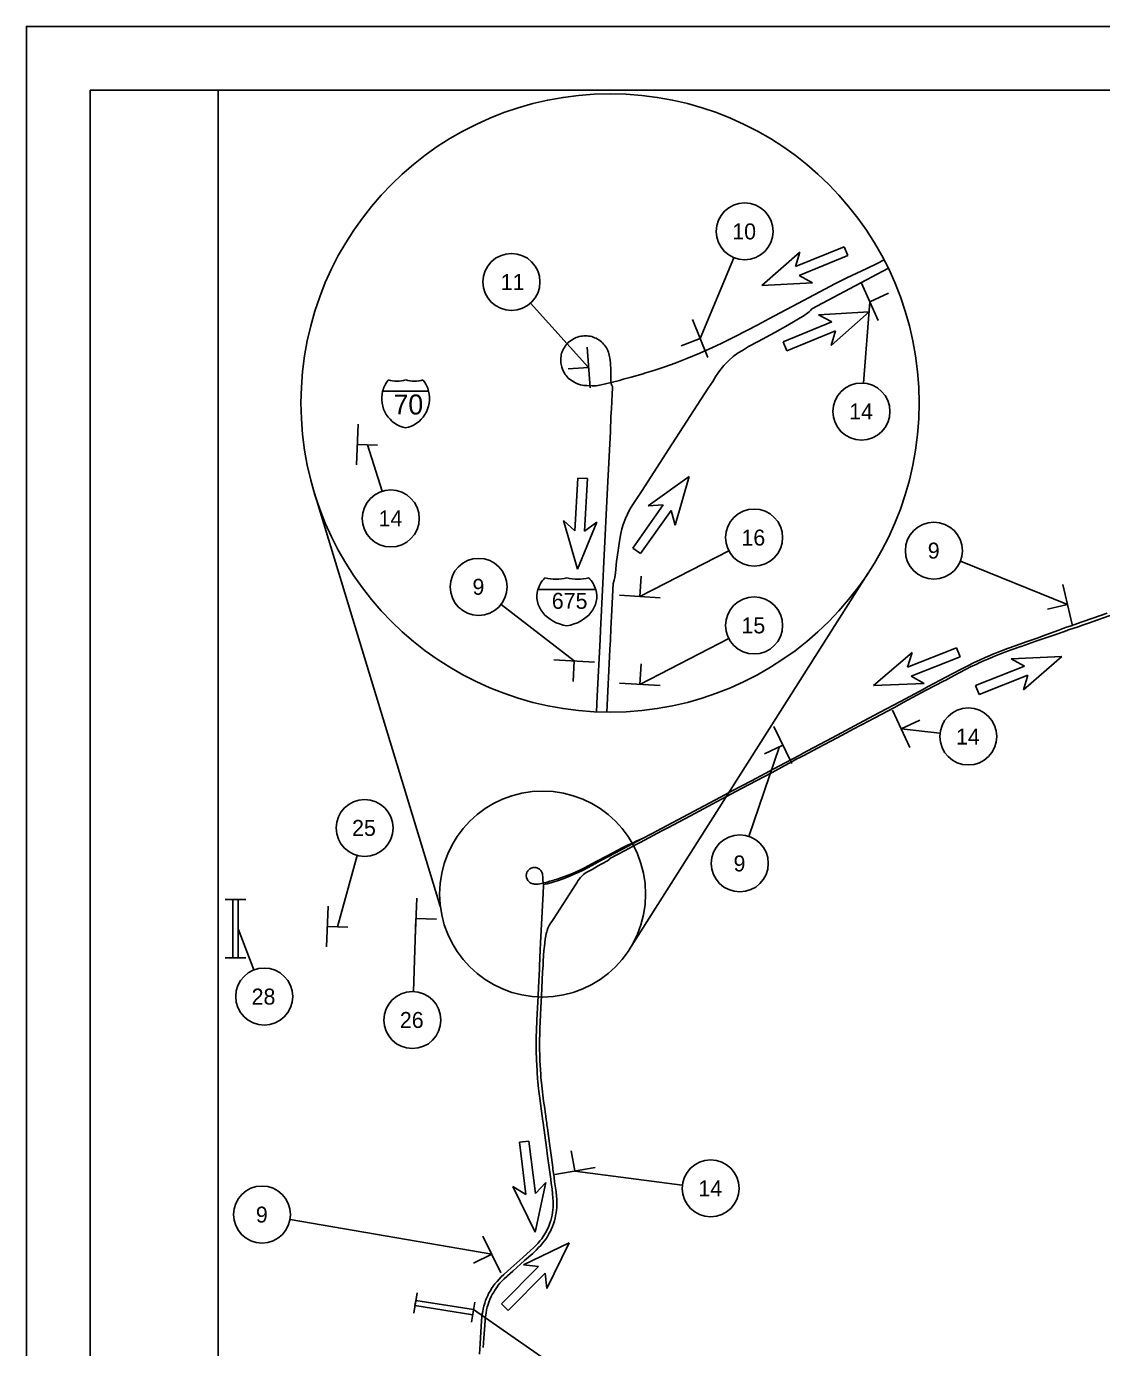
# Model space of a CAD drawing. Extents: x 632.2 to 666.2, y -36.3 to -14.3.
# Drawn here: x 632.19 to 640.6, y -24.64 to -14.3 of the extents above; entities that cross this region are included whole.
import ezdxf

# ---------------------------------------------------------------- set-up
doc = ezdxf.new("R2010")
doc.units = 0
for name, color, linetype in [('Default', 7, 'Continuous'), ('GM_X_Township_ROW', 7, 'Continuous'), ('GM_X_Township_Subdivision', 7, 'Continuous'), ('MT_P_Cells', 7, 'Continuous'), ('SH_Border', 7, 'Continuous'), ('SH_Cut_Line', 7, 'Continuous'), ('SH_Text', 7, 'Continuous'), ('SN_P_Signs', 7, 'Continuous')]:
    doc.layers.add(name, color=color, linetype=linetype)

msp = doc.modelspace()

# ---------------------------------------------------------------- linework, layer by layer
at = {"layer": 'Default'}
for centre in [(637.808, -15.906), (635.983, -16.302), (638.722, -17.316), (635.039, -18.153), (637.882, -18.302), (639.289, -18.405), (635.726, -18.688), (637.882, -18.99), (639.558, -19.859), (634.834, -20.575), (637.77, -20.852), (634.048, -21.894), (635.208, -22.078), (637.542, -23.395), (634.031, -23.6)]:
    msp.add_circle(centre, 0.223, dxfattribs=at)
at = {"layer": 'GM_X_Township_ROW'}
for p, q in [((634.975, -17.157), (635.335, -17.157)), ((635.335, -17.157), (634.975, -17.157)), ((635.335, -17.157), (634.975, -17.157)), ((636.643, -18.709), (636.19, -18.709)), ((636.643, -18.709), (636.19, -18.709))]:
    msp.add_line(p, q, dxfattribs=at)
for centre, start, end in [((635.202, -17.215), 165.8066, 258.463), ((635.202, -17.215), 141.669, 165.8066), ((635.087, -16.845), 253.0091, 286.9909), ((635.224, -16.845), 253.0091, 286.9909), ((635.108, -17.215), 281.537, 14.1934), ((635.108, -17.215), 14.1934, 38.331)]:
    msp.add_arc(centre, 0.234, start, end, dxfattribs=at)
for centre, start_param, end_param in [((636.475, -18.763), 2.911027, 4.511031), ((636.475, -18.763), 2.47259, 2.911027), ((636.331, -18.393), 4.415841, 5.008937), ((636.502, -18.393), 4.415841, 5.008937), ((636.358, -18.763), 4.913747, 6.513751), ((636.358, -18.763), 0.230566, 0.669003)]:
    msp.add_ellipse(centre, major_axis=(0.293, 0), ratio=0.8, start_param=start_param, end_param=end_param, dxfattribs=at)
at = {"layer": 'GM_X_Township_Subdivision'}
for p, q in [((637.942, -16.33), (638.24, -16.068)), ((638.206, -16.182), (638.587, -16.026)), ((638.24, -16.068), (638.206, -16.182)), ((638.616, -16.095), (638.234, -16.251)), ((638.587, -16.026), (638.616, -16.095)), ((638.602, -16.061), (638.602, -16.061)), ((638.338, -16.309), (637.942, -16.33)), ((637.942, -16.33), (637.942, -16.33)), ((638.234, -16.251), (638.338, -16.309)), ((638.387, -16.558), (638.783, -16.537)), ((638.783, -16.537), (638.485, -16.799)), ((638.783, -16.537), (638.783, -16.537)), ((638.109, -16.771), (638.491, -16.615)), ((638.491, -16.615), (638.387, -16.558)), ((638.52, -16.685), (638.138, -16.841)), ((638.485, -16.799), (638.52, -16.685)), ((638.138, -16.841), (638.109, -16.771)), ((638.124, -16.806), (638.124, -16.806)), ((636.479, -18.249), (636.502, -17.837)), ((636.502, -17.837), (636.577, -17.841)), ((636.54, -17.839), (636.54, -17.839)), ((636.577, -17.841), (636.554, -18.253)), ((637.052, -18.055), (637.375, -17.824)), ((637.375, -17.824), (637.265, -18.205)), ((637.375, -17.824), (637.375, -17.824)), ((636.933, -18.384), (637.171, -18.047)), ((637.232, -18.09), (636.994, -18.427)), ((637.171, -18.047), (637.052, -18.055)), ((637.265, -18.205), (637.232, -18.09)), ((636.499, -18.55), (636.39, -18.169)), ((636.39, -18.169), (636.479, -18.249)), ((636.65, -18.183), (636.499, -18.55)), ((636.554, -18.253), (636.65, -18.183)), ((636.994, -18.427), (636.933, -18.384)), ((636.963, -18.406), (636.963, -18.406)), ((636.499, -18.55), (636.499, -18.55)), ((638.817, -19.461), (639.119, -19.202)), ((639.083, -19.316), (639.467, -19.165)), ((639.119, -19.202), (639.083, -19.316)), ((639.467, -19.165), (639.494, -19.235)), ((639.48, -19.2), (639.48, -19.2)), ((639.494, -19.235), (639.11, -19.386)), ((639.614, -19.461), (639.998, -19.309)), ((639.894, -19.251), (640.291, -19.234)), ((639.998, -19.309), (639.894, -19.251)), ((640.291, -19.234), (639.99, -19.493)), ((640.291, -19.234), (640.291, -19.234)), ((639.11, -19.386), (639.214, -19.445)), ((640.025, -19.379), (639.642, -19.53)), ((639.99, -19.493), (640.025, -19.379)), ((639.214, -19.445), (638.817, -19.461)), ((638.817, -19.461), (638.817, -19.461)), ((639.642, -19.53), (639.614, -19.461)), ((639.628, -19.496), (639.628, -19.496)), ((636.046, -23.034), (636.12, -23.025)), ((636.095, -23.444), (636.046, -23.034)), ((636.083, -23.03), (636.083, -23.03)), ((636.12, -23.025), (636.17, -23.435)), ((636.253, -23.349), (636.169, -23.737)), ((636.17, -23.435), (636.253, -23.349)), ((636.169, -23.737), (635.994, -23.38)), ((635.994, -23.38), (636.095, -23.444)), ((636.169, -23.737), (636.169, -23.737)), ((636.077, -23.994), (636.434, -23.821)), ((636.434, -23.821), (636.261, -24.178)), ((636.434, -23.821), (636.434, -23.821)), ((635.904, -24.298), (636.195, -24.006)), ((636.248, -24.059), (635.957, -24.351)), ((636.195, -24.006), (636.077, -23.994)), ((636.261, -24.178), (636.248, -24.059)), ((635.957, -24.351), (635.904, -24.298)), ((635.93, -24.325), (635.93, -24.325))]:
    msp.add_line(p, q, dxfattribs=at)
at = {"layer": 'MT_P_Cells'}
for p, q in [((633.744, -21.134), (633.904, -21.134)), ((633.824, -21.363), (633.824, -21.363)), ((633.744, -21.592), (633.904, -21.592)), ((635.244, -24.213), (635.219, -24.371)), ((635.696, -24.285), (635.671, -24.443)), ((635.457, -24.328), (635.457, -24.328))]:
    msp.add_line(p, q, dxfattribs=at)
for points in [[(633.804, -21.134), (633.844, -21.134), (633.844, -21.592), (633.804, -21.592)], [(635.687, -24.344), (635.681, -24.384), (635.228, -24.311), (635.234, -24.272)]]:
    msp.add_lwpolyline(points, close=True, dxfattribs=at)
at = {"layer": 'SH_Border'}
for points in [[(632.687, -14.802), (633.687, -14.802), (633.687, -35.802), (632.687, -35.802)], [(633.687, -14.802), (665.687, -14.802), (665.687, -35.802), (633.687, -35.802)]]:
    msp.add_lwpolyline(points, close=True, dxfattribs=at)
at = {"layer": 'SH_Cut_Line'}
msp.add_lwpolyline([(632.187, -36.302), (666.187, -36.302), (666.187, -14.302), (632.187, -14.302)], close=True, dxfattribs=at)
at = {"layer": 'SH_Text'}
for p, q in [((637.723, -16.112), (637.461, -16.744)), ((636.133, -16.468), (636.587, -16.971)), ((638.739, -17.093), (638.788, -16.457)), ((634.971, -17.94), (634.856, -17.577)), ((635.426, -21.187), (634.441, -17.954)), ((637.683, -18.405), (636.988, -18.763)), ((639.496, -18.488), (640.335, -18.826)), ((636.908, -21.524), (638.773, -18.583)), ((635.903, -18.825), (636.474, -19.268)), ((637.683, -19.092), (636.988, -19.451)), ((639.336, -19.834), (639.033, -19.799)), ((637.841, -20.641), (638.08, -19.938)), ((634.775, -20.79), (634.622, -21.349)), ((635.216, -21.855), (635.236, -21.283)), ((633.968, -21.686), (633.844, -21.363)), ((637.32, -23.37), (636.478, -23.261)), ((634.251, -23.638), (635.829, -23.911)), ((636.502, -24.909), (635.687, -24.344))]:
    msp.add_line(p, q, dxfattribs=at)
for points in [[(636.649, -19.666), (636.655, -19.544), (636.678, -19.099), (636.681, -19.029), (636.697, -18.66), (636.706, -18.493), (636.735, -17.914), (636.757, -17.471), (636.762, -17.354), (636.765, -17.296), (636.77, -17.181), (636.773, -17.13), (636.773, -17.125), (636.773, -17.117), (636.768, -17.111), (636.766, -17.105), (636.764, -17.096), (636.764, -17.088), (636.762, -17.076), (636.76, -17.019), (636.76, -16.998), (636.757, -16.936), (636.753, -16.899), (636.749, -16.875), (636.742, -16.851), (636.738, -16.839), (636.732, -16.828), (636.726, -16.817), (636.72, -16.807), (636.712, -16.797), (636.704, -16.788), (636.696, -16.779), (636.687, -16.77), (636.677, -16.763), (636.667, -16.755), (636.657, -16.749), (636.646, -16.743), (636.634, -16.738), (636.623, -16.734), (636.611, -16.73), (636.599, -16.727), (636.587, -16.725), (636.575, -16.724), (636.562, -16.723), (636.55, -16.724), (636.537, -16.725), (636.525, -16.727), (636.513, -16.729), (636.501, -16.733), (636.49, -16.737), (636.479, -16.742), (636.468, -16.748), (636.457, -16.754), (636.437, -16.769), (636.428, -16.777), (636.419, -16.786), (636.411, -16.795), (636.403, -16.805), (636.397, -16.815), (636.39, -16.826), (636.385, -16.837), (636.38, -16.848), (636.376, -16.86), (636.373, -16.872), (636.371, -16.884), (636.37, -16.897), (636.369, -16.909), (636.369, -16.921), (636.37, -16.934), (636.372, -16.946), (636.374, -16.958), (636.377, -16.97), (636.386, -16.993), (636.397, -17.015), (636.404, -17.025), (636.411, -17.035), (636.419, -17.045), (636.428, -17.054), (636.437, -17.062), (636.457, -17.077), (636.478, -17.089), (636.501, -17.099), (636.524, -17.106), (636.549, -17.111), (636.561, -17.112), (636.573, -17.113), (636.615, -17.114), (636.646, -17.115), (636.684, -17.107), (636.764, -17.088), (636.775, -17.086), (636.828, -17.073), (636.858, -17.064), (636.921, -17.046), (637.013, -17.02), (637.023, -17.017), (637.098, -16.995), (637.184, -16.966), (637.263, -16.937), (637.355, -16.902), (637.458, -16.86), (637.557, -16.815), (637.625, -16.783), (637.733, -16.728), (637.91, -16.638), (637.998, -16.591), (638.269, -16.446), (638.52, -16.314), (638.608, -16.27), (638.764, -16.196), (638.846, -16.157), (638.901, -16.13)], [(638.333, -16.513), (638.674, -16.333), (638.933, -16.195)], [(636.779, -18.661), (636.788, -18.636), (636.793, -18.614), (636.798, -18.578), (636.806, -18.49), (636.817, -18.404), (636.828, -18.331), (636.839, -18.27), (636.848, -18.234), (636.858, -18.199), (636.875, -18.152), (636.891, -18.119), (636.908, -18.086), (636.933, -18.044), (637.001, -17.941), (637.242, -17.568), (637.523, -17.133), (637.558, -17.082), (637.583, -17.039), (637.614, -16.994), (637.644, -16.957), (637.681, -16.918), (637.717, -16.886), (637.757, -16.857), (637.79, -16.838), (637.838, -16.808), (637.913, -16.768), (638.044, -16.697), (638.146, -16.64), (638.275, -16.564), (638.303, -16.544), (638.314, -16.536), (638.323, -16.526), (638.333, -16.513)], [(640.418, -19), (640.452, -18.989), (640.498, -18.973), (640.571, -18.947), (640.66, -18.916), (640.738, -18.888), (640.778, -18.875), (640.807, -18.864), (640.877, -18.84), (641.016, -18.791), (641.178, -18.734), (641.364, -18.669), (641.43, -18.646), (641.48, -18.629), (641.512, -18.619), (641.543, -18.61), (641.583, -18.6), (641.619, -18.592), (641.651, -18.586), (641.68, -18.581), (641.712, -18.576), (641.748, -18.572)], [(636.729, -19.668), (636.754, -19.178), (636.758, -19.103), (636.762, -19.015), (636.767, -18.921), (636.779, -18.661)], [(636.234, -21.018), (636.261, -21.011), (636.263, -21.011), (636.291, -21.003), (636.322, -20.994), (636.35, -20.985), (636.381, -20.975), (636.415, -20.962), (636.45, -20.948), (636.48, -20.935), (636.51, -20.921), (636.539, -20.907), (636.583, -20.884), (636.688, -20.828), (636.847, -20.744), (636.97, -20.678), (637.009, -20.658), (637.079, -20.621), (637.452, -20.422), (637.618, -20.333), (637.709, -20.285), (637.861, -20.205), (638.075, -20.091), (638.234, -20.007), (638.239, -20.004), (638.248, -19.999), (638.295, -19.974), (638.448, -19.893), (638.531, -19.849), (638.701, -19.757), (638.864, -19.671), (639.027, -19.585), (639.214, -19.485), (639.24, -19.471), (639.436, -19.367), (639.498, -19.335), (639.549, -19.309), (639.604, -19.281), (639.645, -19.262), (639.689, -19.242), (639.734, -19.222), (639.738, -19.221), (639.772, -19.206), (639.818, -19.188), (639.864, -19.171), (639.933, -19.146), (640.011, -19.119), (640.096, -19.089), (640.166, -19.063), (640.267, -19.026), (640.319, -19.007), (640.346, -18.998), (640.354, -18.995), (640.448, -18.962), (640.533, -18.932), (640.645, -18.893)], [(640.331, -19.03), (640.335, -19.028), (640.343, -19.025), (640.418, -19)], [(639.969, -19.155), (639.971, -19.155), (640.029, -19.134), (640.087, -19.114), (640.188, -19.079), (640.25, -19.057), (640.331, -19.03)], [(639.711, -19.253), (639.721, -19.249), (639.729, -19.245), (639.771, -19.227), (639.771, -19.227)], [(639.771, -19.227), (639.809, -19.212), (639.843, -19.199), (639.901, -19.179), (639.969, -19.155)], [(639.368, -19.424), (639.376, -19.42), (639.448, -19.381), (639.536, -19.335), (639.576, -19.315), (639.624, -19.292), (639.638, -19.285)], [(639.638, -19.285), (639.673, -19.27), (639.711, -19.253)], [(639.054, -19.591), (639.224, -19.5), (639.368, -19.424)], [(638.646, -19.808), (638.728, -19.765), (638.826, -19.712), (638.98, -19.631)], [(638.98, -19.631), (639.018, -19.61), (639.054, -19.591)], [(637.213, -20.57), (637.251, -20.55), (637.385, -20.479), (637.555, -20.388), (637.631, -20.348), (637.74, -20.29), (637.837, -20.238), (638.022, -20.14), (638.152, -20.07), (638.185, -20.053), (638.217, -20.035), (638.24, -20.023), (638.272, -20.007), (638.377, -19.951), (638.533, -19.869), (638.634, -19.814), (638.646, -19.808)], [(636.991, -20.688), (637.161, -20.598), (637.213, -20.57)], [(636.208, -22.711), (636.202, -22.671), (636.198, -22.634), (636.195, -22.614), (636.193, -22.59), (636.189, -22.557), (636.188, -22.541), (636.186, -22.524), (636.184, -22.499), (636.183, -22.475), (636.178, -22.39), (636.176, -22.32), (636.176, -22.247), (636.177, -22.21), (636.178, -22.16), (636.182, -22.078), (636.191, -21.889), (636.194, -21.824), (636.202, -21.676), (636.203, -21.653), (636.208, -21.53), (636.211, -21.474), (636.221, -21.281), (636.228, -21.133), (636.23, -21.094), (636.231, -21.075), (636.233, -21.037), (636.234, -21.02), (636.234, -21.018), (636.234, -21.015), (636.232, -21.013), (636.231, -21.011), (636.231, -21.008), (636.23, -21.006), (636.23, -21.002), (636.229, -20.983), (636.229, -20.976), (636.228, -20.955), (636.227, -20.943), (636.226, -20.935), (636.223, -20.927), (636.222, -20.923), (636.22, -20.919), (636.218, -20.916), (636.216, -20.912), (636.213, -20.909), (636.211, -20.906), (636.208, -20.903), (636.205, -20.9), (636.202, -20.897), (636.198, -20.895), (636.195, -20.893), (636.191, -20.891), (636.187, -20.889), (636.184, -20.888), (636.18, -20.886), (636.176, -20.885), (636.172, -20.885), (636.167, -20.884), (636.163, -20.884), (636.159, -20.884), (636.155, -20.885), (636.151, -20.885), (636.147, -20.886), (636.143, -20.887), (636.139, -20.889), (636.135, -20.89), (636.132, -20.892), (636.128, -20.895), (636.122, -20.899), (636.119, -20.902), (636.116, -20.905), (636.113, -20.908), (636.11, -20.911), (636.108, -20.915), (636.106, -20.918), (636.104, -20.922), (636.103, -20.926), (636.101, -20.93), (636.1, -20.934), (636.1, -20.938), (636.099, -20.942), (636.099, -20.946), (636.099, -20.95), (636.099, -20.954), (636.1, -20.958), (636.101, -20.962), (636.102, -20.966), (636.105, -20.974), (636.108, -20.981), (636.111, -20.985), (636.113, -20.988), (636.116, -20.991), (636.119, -20.994), (636.122, -20.997), (636.128, -21.002), (636.135, -21.006), (636.143, -21.009), (636.151, -21.012), (636.159, -21.013), (636.163, -21.014), (636.167, -21.014), (636.181, -21.014), (636.191, -21.015), (636.204, -21.012), (636.23, -21.006), (636.234, -21.005), (636.252, -21.001), (636.262, -20.998), (636.283, -20.992), (636.314, -20.983), (636.317, -20.982), (636.342, -20.975), (636.37, -20.965), (636.397, -20.955), (636.428, -20.944), (636.462, -20.93), (636.495, -20.915), (636.518, -20.904), (636.554, -20.886), (636.613, -20.856), (636.642, -20.84), (636.732, -20.792), (636.816, -20.748), (636.845, -20.733), (636.897, -20.708), (636.924, -20.696), (636.963, -20.676), (636.99, -20.664), (637, -20.661), (637.009, -20.658)], [(636.753, -20.814), (636.867, -20.754), (636.965, -20.702), (636.991, -20.688)], [(636.236, -21.53), (636.238, -21.522), (636.24, -21.514), (636.242, -21.502), (636.245, -21.473), (636.248, -21.444), (636.252, -21.42), (636.256, -21.4), (636.259, -21.388), (636.262, -21.376), (636.268, -21.36), (636.273, -21.349), (636.279, -21.338), (636.287, -21.324), (636.309, -21.29), (636.39, -21.166), (636.483, -21.021), (636.495, -21.004), (636.503, -20.989), (636.514, -20.975), (636.524, -20.962), (636.536, -20.949), (636.548, -20.939), (636.561, -20.929), (636.572, -20.922), (636.589, -20.912), (636.614, -20.899), (636.657, -20.875), (636.691, -20.856), (636.734, -20.831), (636.744, -20.825), (636.747, -20.822), (636.75, -20.818), (636.753, -20.814)], [(636.212, -22.501), (636.207, -22.432), (636.206, -22.398), (636.204, -22.363), (636.204, -22.34), (636.203, -22.32), (636.203, -22.3), (636.203, -22.273), (636.203, -22.239), (636.203, -22.22), (636.204, -22.201), (636.204, -22.186), (636.206, -22.145), (636.216, -21.931), (636.218, -21.892), (636.227, -21.702), (636.229, -21.677), (636.23, -21.648), (636.232, -21.617), (636.236, -21.53)], [(636.235, -22.714), (636.22, -22.592), (636.214, -22.528), (636.212, -22.501)], [(635.732, -24.692), (635.737, -24.609), (635.746, -24.475), (635.749, -24.433), (635.752, -24.403), (635.755, -24.378), (635.758, -24.359), (635.762, -24.337), (635.768, -24.316), (635.774, -24.294), (635.781, -24.273), (635.789, -24.254), (635.797, -24.234), (635.807, -24.214), (635.818, -24.196), (635.828, -24.178), (635.84, -24.161), (635.854, -24.143), (635.87, -24.124), (635.886, -24.105), (635.903, -24.088), (635.923, -24.068), (635.954, -24.041), (636.073, -23.935), (636.133, -23.881), (636.155, -23.86), (636.174, -23.842), (636.191, -23.823), (636.206, -23.806), (636.22, -23.789), (636.231, -23.772), (636.25, -23.744), (636.268, -23.709), (636.275, -23.692), (636.286, -23.661), (636.291, -23.646), (636.297, -23.625), (636.301, -23.604), (636.305, -23.584), (636.308, -23.563), (636.309, -23.542), (636.31, -23.52), (636.31, -23.496), (636.308, -23.47), (636.305, -23.439), (636.301, -23.4), (636.295, -23.357), (636.29, -23.322), (636.278, -23.231), (636.266, -23.144), (636.257, -23.075), (636.231, -22.883), (636.229, -22.87), (636.229, -22.87), (636.218, -22.792), (636.208, -22.711)], [(636.247, -22.796), (636.243, -22.77), (636.235, -22.714)], [(636.251, -22.831), (636.247, -22.796)], [(636.259, -22.886), (636.257, -22.87), (636.255, -22.858), (636.251, -22.831)], [(636.264, -22.923), (636.261, -22.898), (636.259, -22.886)], [(636.301, -23.192), (636.296, -23.154), (636.28, -23.043), (636.264, -22.923)], [(636.308, -23.246), (636.306, -23.233), (636.301, -23.192)], [(636.317, -23.311), (636.317, -23.311), (636.308, -23.246)], [(636.279, -23.746), (636.289, -23.729), (636.294, -23.717), (636.304, -23.694), (636.312, -23.673), (636.319, -23.649), (636.325, -23.628), (636.329, -23.607), (636.333, -23.587), (636.336, -23.566), (636.337, -23.546), (636.338, -23.524), (636.338, -23.502), (636.337, -23.48), (636.335, -23.455), (636.332, -23.422), (636.321, -23.344), (636.317, -23.311)], [(635.952, -24.08), (635.993, -24.043), (636.086, -23.96), (636.15, -23.904), (636.177, -23.878), (636.196, -23.859), (636.213, -23.842), (636.227, -23.825), (636.24, -23.809), (636.252, -23.792), (636.262, -23.776), (636.279, -23.746)], [(635.865, -24.174), (635.868, -24.17), (635.88, -24.154), (635.893, -24.138), (635.909, -24.121), (635.926, -24.104), (635.946, -24.085), (635.952, -24.08)], [(635.851, -24.196), (635.856, -24.188), (635.865, -24.174)], [(635.763, -24.641), (635.768, -24.568), (635.774, -24.465), (635.777, -24.426), (635.78, -24.397), (635.784, -24.371), (635.789, -24.347), (635.794, -24.325), (635.8, -24.304), (635.806, -24.285), (635.813, -24.266), (635.822, -24.247), (635.825, -24.241)], [(635.825, -24.241), (635.832, -24.227), (635.844, -24.207), (635.851, -24.196)]]:
    msp.add_lwpolyline(points, dxfattribs=at)
for centre, radius in [((636.755, -17.249), 2.419), ((636.227, -21.092), 0.806)]:
    msp.add_circle(centre, radius, dxfattribs=at)
at = {"layer": 'SN_P_Signs'}
for p, q in [((638.854, -16.603), (638.722, -16.311)), ((638.788, -16.457), (638.934, -16.391)), ((637.401, -16.595), (637.52, -16.893)), ((637.461, -16.744), (637.312, -16.803)), ((636.576, -16.812), (636.599, -17.131)), ((636.587, -16.971), (636.428, -16.983)), ((634.77, -17.734), (634.783, -17.414)), ((634.777, -17.574), (634.936, -17.58)), ((636.988, -18.763), (636.998, -18.604)), ((640.298, -18.67), (640.372, -18.982)), ((637.148, -18.774), (636.829, -18.753)), ((640.335, -18.826), (640.179, -18.863)), ((636.315, -19.259), (636.634, -19.278)), ((636.474, -19.268), (636.465, -19.428)), ((636.988, -19.451), (636.998, -19.291)), ((637.148, -19.461), (636.829, -19.441)), ((639.1, -19.944), (638.965, -19.654)), ((639.033, -19.799), (639.178, -19.731)), ((638.036, -19.782), (638.176, -20.07)), ((638.106, -19.926), (637.962, -19.996)), ((634.536, -21.506), (634.548, -21.186)), ((635.23, -21.443), (635.242, -21.123)), ((635.236, -21.283), (635.396, -21.289)), ((634.542, -21.346), (634.702, -21.352)), ((636.479, -23.259), (636.451, -23.102)), ((636.637, -23.231), (636.322, -23.287)), ((635.759, -23.768), (635.899, -24.055)), ((635.829, -23.911), (635.686, -23.981))]:
    msp.add_line(p, q, dxfattribs=at)

# ---------------------------------------------------------------- texts
at = {"layer": 'Default'}
for s, p in [('10', (637.711, -15.969)), ('11', (635.899, -16.365)), ('14', (638.626, -17.378)), ('14', (634.943, -18.215)), ('16', (637.783, -18.365)), ('9', (639.241, -18.467)), ('9', (635.678, -18.75)), ('15', (637.783, -19.052)), ('14', (639.462, -19.922)), ('25', (634.736, -20.637)), ('9', (637.721, -20.915)), ('28', (633.95, -21.957)), ('26', (635.11, -22.14)), ('14', (637.446, -23.457)), ('9', (633.983, -23.663))]:
    msp.add_text(s, height=0.125, dxfattribs=at).set_placement(p)
at = {"layer": 'GM_X_Township_ROW'}
for s, height, p in [('70', 0.1562, (635.06, -17.339)), ('675', 0.125, (636.299, -18.86))]:
    msp.add_text(s, height=height, dxfattribs=at).set_placement(p)

doc.saveas('drawing.dxf')
